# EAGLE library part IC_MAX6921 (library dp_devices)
20-outputs, 76V, serial VFD driver Dangerousprototypes.com
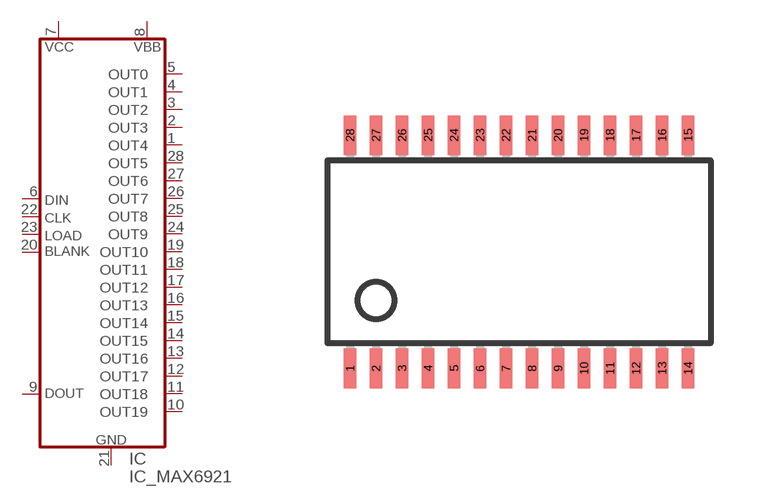
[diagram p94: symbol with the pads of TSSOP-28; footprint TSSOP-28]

Designator prefix IC

## IC_MAX6921-TSSOP28  [TSSOP-28]
1  OUT4  out
2  OUT3  out
3  OUT2  out
4  OUT1  out
5  OUT0  out
6  DIN  in
7  VCC  pwr
8  VBB  pwr
9  DOUT  out
10  OUT19  out
11  OUT18  out
12  OUT17  out
13  OUT16  out
14  OUT15  out
15  OUT14  out
16  OUT13  out
17  OUT12  out
18  OUT11  out
19  OUT10  out
20  BLANK  in
21  GND  pwr
22  CLK  in
23  LOAD  in
24  OUT9  out
25  OUT8  out
26  OUT7  out
27  OUT6  out
28  OUT5  out

## Footprint TSSOP-28 (pad centres in mm)
Thin Shrink Small Outline Plastic 28 (TSSOP28)
smd 0.305 x 0.991: 1 -4.225,-2.918; 2 -3.575,-2.918; 3 -2.925,-2.918; 4 -2.275,-2.918; 5 -1.625,-2.918; 6 -0.975,-2.918; 7 -0.325,-2.918; 8 0.325,-2.918; 9 0.975,-2.918; 10 1.625,-2.918; 11 2.275,-2.918; 12 2.925,-2.918; 13 3.575,-2.918; 14 4.225,-2.918; 15 4.225,2.918; 16 3.575,2.918; 17 2.925,2.918; 18 2.275,2.918; 19 1.625,2.918; 20 0.975,2.918; 21 0.325,2.918; 22 -0.325,2.918; 23 -0.975,2.918; 24 -1.625,2.918; 25 -2.275,2.918; 26 -2.925,2.918; 27 -3.575,2.918; 28 -4.225,2.918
